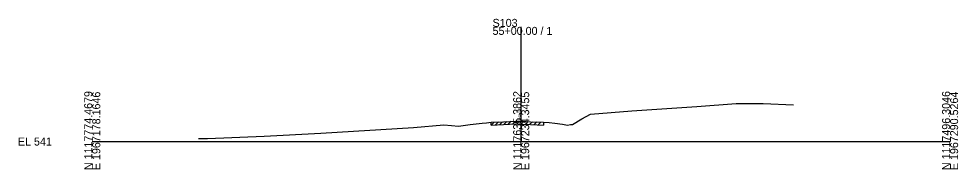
# Model space of a CAD drawing. Extents: x 974 to 1303, y 990 to 14518.
# Drawn here: x 974.3 to 1302.8, y 3490.3 to 3543 of the extents above; entities that cross this region are included whole.
import ezdxf

# ---------------------------------------------------------------- set-up
doc = ezdxf.new("R2010")
doc.units = 0
for name, color, linetype in [('Level 10', 7, 'Continuous'), ('Level 60', 7, 'Continuous'), ('Level 61', 7, 'Continuous'), ('Level 63', 7, 'Continuous')]:
    doc.layers.add(name, color=color, linetype=linetype)

msp = doc.modelspace()

# ---------------------------------------------------------------- linework, layer by layer
at = {"layer": 'Level 60'}
for p, q in [((1188.66, 3510.75), (1211.43, 3512.33)), ((1211.43, 3512.33), (1225.24, 3513.31)), ((1225.24, 3513.31), (1234.59, 3513.39)), ((1234.59, 3513.39), (1245.21, 3512.86)), ((1171.23, 3507.94), (1174.29, 3509.55)), ((1174.29, 3509.55), (1188.66, 3510.75)), ((1112.33, 3504.98), (1122.93, 3505.81)), ((1122.93, 3505.81), (1125.66, 3505.6)), ((1125.66, 3505.6), (1128.05, 3505.42)), ((1128.05, 3505.42), (1132.15, 3505.96)), ((1132.15, 3505.96), (1136.31, 3506.46)), ((1136.31, 3506.46), (1137.84, 3506.61)), ((1137.84, 3506.61), (1139.47, 3506.76)), ((1139.47, 3506.76), (1143.8, 3506.96)), ((1143.8, 3506.96), (1148.18, 3507.17)), ((1148.18, 3507.17), (1150, 3507.09)), ((1150, 3507.09), (1153.27, 3506.96)), ((1153.27, 3506.96), (1157.83, 3506.77)), ((1157.83, 3506.77), (1159.84, 3506.65)), ((1159.84, 3506.65), (1161.8, 3506.5)), ((1161.8, 3506.5), (1164.47, 3506.11)), ((1164.47, 3506.11), (1166.19, 3505.78)), ((1166.19, 3505.78), (1167.24, 3505.93)), ((1167.24, 3505.93), (1167.94, 3506.03)), ((1167.94, 3506.03), (1171.23, 3507.94)), ((1060.07, 3501.92), (1079.98, 3502.94)), ((1079.98, 3502.94), (1112.33, 3504.98)), ((1037.13, 3501.02), (1040.32, 3501.1)), ((1040.32, 3501.1), (1060.07, 3501.92))]:
    msp.add_line(p, q, dxfattribs=at)
at = {"layer": 'Level 61'}
for p, q in [((1139.47, 3505.76), (1140.52, 3506.81)), ((1139.47, 3505.76), (1139.47, 3506.76)), ((1139.47, 3505.76), (1143.8, 3505.96)), ((1139.47, 3505.76), (1139.47, 3505.76)), ((1140.97, 3505.83), (1142.02, 3506.88)), ((1142.47, 3505.9), (1143.52, 3506.95)), ((1143.8, 3505.96), (1148.18, 3506.17)), ((1143.97, 3505.97), (1145.02, 3507.02)), ((1145.47, 3506.04), (1146.52, 3507.09)), ((1146.97, 3506.11), (1148.02, 3507.16)), ((1148.18, 3506.17), (1150, 3506.09)), ((1148.47, 3506.16), (1149.43, 3507.12)), ((1149.97, 3506.09), (1150.93, 3507.06)), ((1150, 3506.09), (1153.27, 3505.96)), ((1151.47, 3506.03), (1152.43, 3506.99)), ((1152.97, 3505.97), (1153.93, 3506.93)), ((1153.27, 3505.96), (1157.83, 3505.77)), ((1154.47, 3505.91), (1155.43, 3506.87)), ((1155.97, 3505.85), (1156.93, 3506.81)), ((1157.83, 3506.77), (1157.83, 3505.77))]:
    msp.add_line(p, q, dxfattribs=at)
at = {"layer": 'Level 63'}
for p, q in [((1150, 3500), (1150, 3540.17)), ((1000, 3500), (1150, 3500)), ((1150, 3500), (1300, 3500))]:
    msp.add_line(p, q, dxfattribs=at)

# ---------------------------------------------------------------- texts
at = {"layer": 'Level 10'}
msp.add_text('548.09', height=0.9, rotation=90, dxfattribs=at).set_placement((1149.95, 3507.59))
at = {"layer": 'Level 63'}
for s, p in [('S103', (1140, 3540.17)), ('55+00.00 / 1', (1140, 3537.37)), ('EL 541', (974, 3498.6))]:
    msp.add_text(s, height=2.8, dxfattribs=at).set_placement(p)
for s, p in [('N 1117774.4679', (1000, 3490)), ('E 1967178.1646', (1002.8, 3490)), ('N 1117635.3862', (1150, 3490)), ('E 1967234.3455', (1152.8, 3490)), ('N 1117496.3046', (1300, 3490)), ('E 1967290.5264', (1302.8, 3490))]:
    msp.add_text(s, height=2.8, rotation=90, dxfattribs=at).set_placement(p)

doc.saveas('drawing.dxf')
